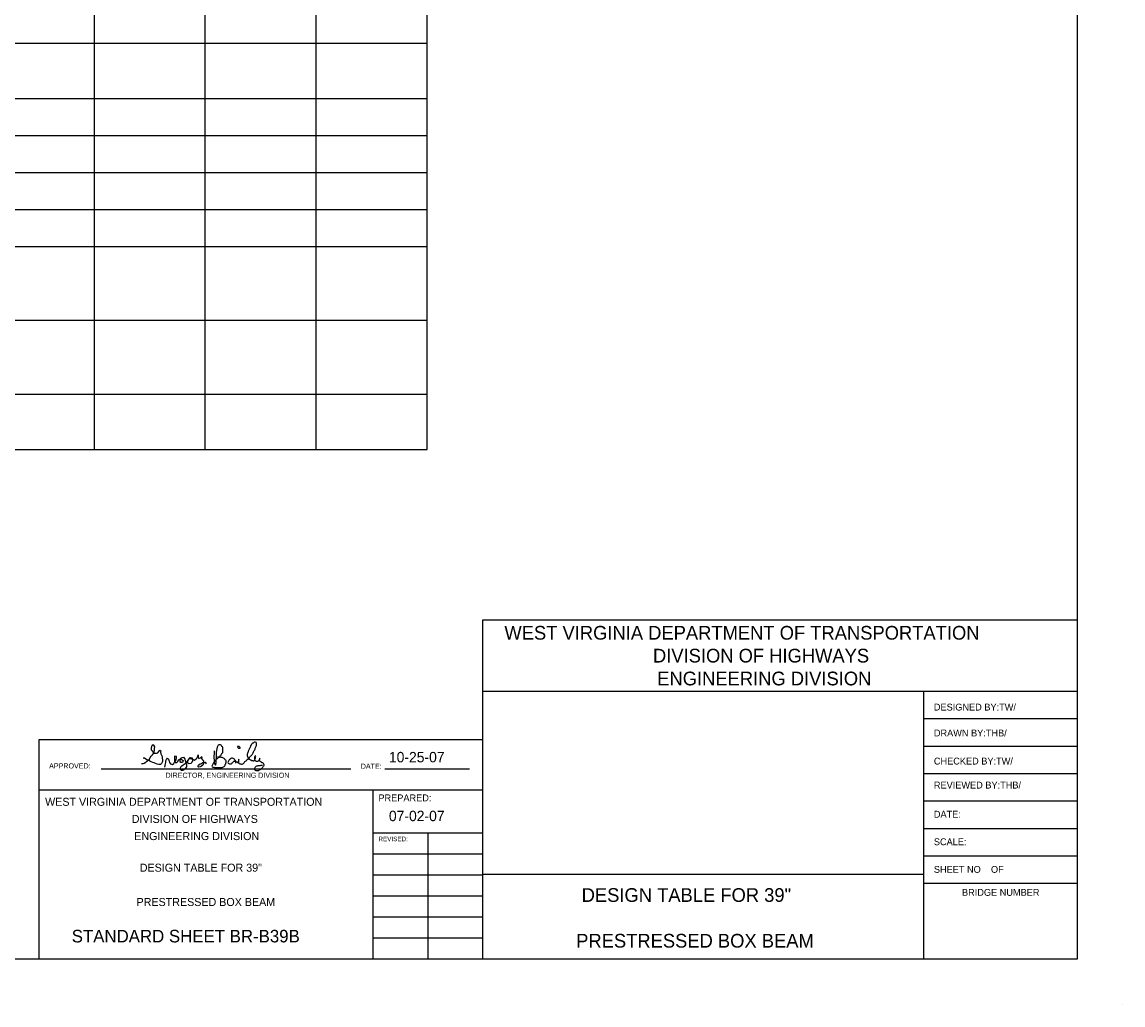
# Model space of a CAD drawing. Extents: x 762.3 to 790.4, y -1210.3 to -1192.2.
# Drawn here: x 780.44 to 790.37, y -1210.35 to -1201.48 of the extents above; entities that cross this region are included whole.
import ezdxf

# ---------------------------------------------------------------- set-up
doc = ezdxf.new("R2010")
doc.units = 0
for name, color, linetype in [('CURBLINE', 7, 'Continuous'), ('Default', 7, 'Continuous'), ('Level 1', 7, 'Continuous')]:
    doc.layers.add(name, color=color, linetype=linetype)

msp = doc.modelspace()

# ---------------------------------------------------------------- linework, layer by layer
at = {"layer": 'CURBLINE'}
msp.add_line((789.9542, -1206.8764), (784.5917, -1206.8755), dxfattribs=at)
at = {"layer": 'Default'}
for p, q in [((789.9542, -1192.6096), (789.9542, -1209.9346)), ((784.0909, -1205.3356), (784.0909, -1193.1689)), ((781.0909, -1205.3356), (781.0909, -1193.6689)), ((782.0909, -1205.3356), (782.0909, -1193.6689)), ((783.0909, -1205.3356), (783.0909, -1193.6689)), ((764.5075, -1201.6689), (784.0909, -1201.6689)), ((764.5075, -1202.1689), (784.0909, -1202.1689)), ((766.2575, -1202.5023), (784.0909, -1202.5023)), ((766.2575, -1202.8356), (784.0909, -1202.8356)), ((764.5075, -1203.1689), (784.0909, -1203.1689)), ((766.2575, -1203.5023), (784.0909, -1203.5023)), ((766.2575, -1204.1689), (784.0909, -1204.1689)), ((764.5075, -1204.8356), (784.0909, -1204.8356)), ((764.5075, -1205.3356), (784.0909, -1205.3356)), ((784.5917, -1206.8755), (784.5917, -1209.9346)), ((784.5917, -1206.9415), (784.5917, -1206.9415)), ((788.5682, -1207.519), (784.5917, -1207.519)), ((788.5682, -1207.519), (788.5682, -1209.9346)), ((789.9542, -1207.519), (788.5682, -1207.519)), ((789.9542, -1207.7665), (788.5682, -1207.7665)), ((784.5917, -1207.9546), (780.5905, -1207.9546)), ((780.5905, -1207.9546), (780.5905, -1209.9346)), ((789.9542, -1208.014), (788.5682, -1208.014)), ((781.152, -1208.2157), (783.4022, -1208.2157)), ((783.7105, -1208.2157), (784.4725, -1208.2157)), ((789.9542, -1208.2615), (788.5682, -1208.2615)), ((783.6017, -1208.4083), (780.5905, -1208.4083)), ((783.6017, -1208.4083), (783.6017, -1209.9346)), ((784.5917, -1208.4083), (783.6017, -1208.4083)), ((789.9542, -1208.509), (788.5682, -1208.509)), ((784.5917, -1208.7961), (783.6017, -1208.7961)), ((784.0967, -1208.7961), (784.0967, -1209.9346)), ((789.9542, -1208.7565), (788.5682, -1208.7565)), ((784.5917, -1208.9858), (783.6017, -1208.9858)), ((789.9542, -1209.004), (788.5682, -1209.004)), ((784.5917, -1209.1756), (783.6017, -1209.1756)), ((788.5682, -1209.169), (784.5917, -1209.169)), ((789.9542, -1209.2515), (788.5682, -1209.2515)), ((784.5917, -1209.3653), (783.6017, -1209.3653)), ((784.5917, -1209.5551), (783.6017, -1209.5551)), ((784.5917, -1209.7448), (783.6017, -1209.7448)), ((789.9542, -1209.9346), (763.5542, -1209.9346)), ((790.3667, -1210.3471), (790.3667, -1210.3471))]:
    msp.add_line(p, q, dxfattribs=at)
at = {"layer": 'Level 1'}
for points in [[(781.516, -1208.1669), (781.531, -1208.1694), (781.5407, -1208.1646), (781.5537, -1208.1568), (781.5637, -1208.1468), (781.5763, -1208.1392), (781.5876, -1208.1279), (781.5938, -1208.1128), (781.6026, -1208.1015), (781.6139, -1208.0915), (781.6227, -1208.0789), (781.629, -1208.0651), (781.6315, -1208.0488), (781.634, -1208.0337), (781.6353, -1208.0186), (781.6265, -1208.0036), (781.6127, -1208.0036), (781.6052, -1208.0149), (781.6026, -1208.0287), (781.6026, -1208.0438), (781.6127, -1208.0538), (781.6215, -1208.0664), (781.634, -1208.0739), (781.6504, -1208.0752), (781.6642, -1208.0726), (781.673, -1208.0613), (781.6818, -1208.0475), (781.6893, -1208.0526), (781.6868, -1208.0664), (781.6906, -1208.0802), (781.6956, -1208.0927), (781.7006, -1208.1053), (781.7031, -1208.1204), (781.7056, -1208.1355), (781.7056, -1208.1505), (781.6968, -1208.1669), (781.6868, -1208.1769), (781.6705, -1208.1769), (781.6579, -1208.1735), (781.6428, -1208.1694), (781.6303, -1208.1618), (781.6177, -1208.1586), (781.6039, -1208.1518), (781.5901, -1208.1468), (781.5788, -1208.1392), (781.5662, -1208.1342), (781.5537, -1208.1292), (781.5423, -1208.1216), (781.5298, -1208.1191)], [(782.1701, -1208.0538), (782.1707, -1208.0607), (782.1707, -1208.0676), (782.1707, -1208.0745), (782.1707, -1208.0821), (782.1695, -1208.089), (782.1682, -1208.0959), (782.1682, -1208.1028), (782.1682, -1208.1097), (782.1682, -1208.1166), (782.1688, -1208.1235), (782.1695, -1208.1304), (782.1695, -1208.1373), (782.1701, -1208.1442), (782.1713, -1208.1512), (782.172, -1208.1587), (782.1726, -1208.1656), (782.1745, -1208.1725), (782.1789, -1208.1775), (782.1826, -1208.1832), (782.1845, -1208.1763), (782.187, -1208.17), (782.1889, -1208.1631), (782.1895, -1208.1562), (782.1895, -1208.1493), (782.1895, -1208.1424), (782.1902, -1208.1355), (782.1902, -1208.1285), (782.1908, -1208.1216), (782.1914, -1208.1147), (782.1921, -1208.1078), (782.1921, -1208.1009), (782.1921, -1208.094), (782.1921, -1208.0871), (782.1921, -1208.0802), (782.1921, -1208.0733), (782.1921, -1208.0664), (782.1927, -1208.0595), (782.1939, -1208.0526), (782.1952, -1208.045), (782.1971, -1208.0381), (782.199, -1208.0312), (782.1996, -1208.0243), (782.2021, -1208.018), (782.2046, -1208.0117), (782.2071, -1208.0054), (782.2109, -1207.9992), (782.2172, -1207.9967), (782.2241, -1207.9973), (782.231, -1207.9992), (782.2354, -1208.0042), (782.2385, -1208.0105), (782.2423, -1208.0161), (782.2454, -1208.0224), (782.2467, -1208.0293), (782.2473, -1208.0362), (782.2473, -1208.0431), (782.2473, -1208.05), (782.2473, -1208.0569), (782.2473, -1208.0639), (782.2461, -1208.0708), (782.2423, -1208.0764), (782.2373, -1208.0808), (782.2329, -1208.0858), (782.2304, -1208.0921), (782.2266, -1208.0978), (782.2228, -1208.1034), (782.2203, -1208.1097), (782.2147, -1208.1135), (782.2084, -1208.1166), (782.2027, -1208.121), (782.1965, -1208.1248), (782.1914, -1208.1292), (782.1864, -1208.1342), (782.1826, -1208.1399), (782.1776, -1208.1442), (782.1738, -1208.1499), (782.1701, -1208.1556), (782.1651, -1208.1612), (782.1613, -1208.1669), (782.1588, -1208.1731), (782.155, -1208.1788), (782.1525, -1208.1851), (782.1512, -1208.192), (782.1538, -1208.1983), (782.16, -1208.2008), (782.1669, -1208.2014), (782.1738, -1208.2033), (782.1808, -1208.2045), (782.1877, -1208.2052), (782.1946, -1208.2052), (782.2021, -1208.2052), (782.209, -1208.2052), (782.2159, -1208.2052), (782.2228, -1208.2052), (782.2297, -1208.2052), (782.2367, -1208.2052), (782.2436, -1208.2052), (782.2486, -1208.2001), (782.2549, -1208.1976), (782.2605, -1208.1939), (782.2662, -1208.1888), (782.2687, -1208.1826), (782.2712, -1208.1763), (782.275, -1208.1706), (782.2775, -1208.1643), (782.2794, -1208.1574), (782.2806, -1208.1505), (782.2806, -1208.1436), (782.2762, -1208.1386), (782.2712, -1208.1342), (782.2662, -1208.1292), (782.2618, -1208.1235), (782.2555, -1208.1198), (782.2492, -1208.116), (782.2423, -1208.1147), (782.2354, -1208.1135), (782.2285, -1208.1122), (782.221, -1208.1122), (782.2134, -1208.1122), (782.2065, -1208.1122), (782.1996, -1208.111), (782.1996, -1208.111)], [(782.3855, -1208.0174), (782.3855, -1208.0243), (782.3905, -1208.0287), (782.3974, -1208.0306), (782.4043, -1208.0299), (782.4056, -1208.023), (782.4006, -1208.0186), (782.3955, -1208.0136), (782.3886, -1208.0136), (782.3824, -1208.0161), (782.3824, -1208.0205)], [(782.486, -1208.1204), (782.4898, -1208.1147), (782.4935, -1208.1091), (782.4973, -1208.1034), (782.5017, -1208.0984), (782.5073, -1208.0946), (782.5117, -1208.0896), (782.5155, -1208.0833), (782.5186, -1208.077), (782.523, -1208.0708), (782.5268, -1208.0645), (782.5293, -1208.0582), (782.5331, -1208.0513), (782.5362, -1208.0444), (782.5394, -1208.0375), (782.5419, -1208.0312), (782.5444, -1208.0249), (782.5469, -1208.0186), (782.5488, -1208.0117), (782.5513, -1208.0054), (782.5526, -1207.9985), (782.5538, -1207.9916), (782.5526, -1207.9847), (782.5482, -1207.9797), (782.5419, -1207.9772), (782.535, -1207.9759), (782.5287, -1207.9797), (782.523, -1207.9835), (782.5168, -1207.986), (782.5117, -1207.9904), (782.508, -1207.996), (782.5042, -1208.0017), (782.4992, -1208.0067), (782.4979, -1208.0136), (782.4954, -1208.0199), (782.4929, -1208.0262), (782.4891, -1208.0318), (782.4866, -1208.0381), (782.4828, -1208.0438), (782.4816, -1208.0507), (782.4778, -1208.0563), (782.4766, -1208.0632), (782.4741, -1208.0701), (782.4715, -1208.077), (782.469, -1208.0833), (782.469, -1208.0902), (782.469, -1208.0971), (782.4703, -1208.1041), (782.4734, -1208.1103), (782.4759, -1208.1172), (782.4791, -1208.1235), (782.4841, -1208.1279), (782.4904, -1208.1304), (782.496, -1208.1348), (782.5029, -1208.1361), (782.5092, -1208.1399), (782.5155, -1208.1424), (782.523, -1208.143), (782.53, -1208.143), (782.5337, -1208.1373), (782.5375, -1208.1317), (782.5406, -1208.1248), (782.5431, -1208.1179), (782.5438, -1208.111), (782.5457, -1208.1034), (782.5406, -1208.099), (782.5381, -1208.1059), (782.5356, -1208.1122), (782.5356, -1208.1191), (782.5356, -1208.126), (782.5356, -1208.1329), (782.5381, -1208.1399), (782.5444, -1208.1436), (782.5507, -1208.1461), (782.5576, -1208.1468), (782.5645, -1208.1468), (782.5708, -1208.1442), (782.5745, -1208.138), (782.5789, -1208.1329), (782.5821, -1208.126), (782.584, -1208.1191), (782.5808, -1208.126), (782.5783, -1208.1323), (782.5758, -1208.1386), (782.5783, -1208.1449), (782.5846, -1208.148), (782.5909, -1208.1512), (782.5953, -1208.1562), (782.6022, -1208.1581), (782.6091, -1208.1606), (782.6135, -1208.1656), (782.616, -1208.1719), (782.6185, -1208.1782), (782.6185, -1208.1851), (782.6172, -1208.192), (782.6122, -1208.1964), (782.6085, -1208.202), (782.6034, -1208.2077), (782.5997, -1208.2133), (782.5934, -1208.2177), (782.5884, -1208.2221), (782.5821, -1208.2259), (782.5758, -1208.2297), (782.5701, -1208.2334), (782.5626, -1208.2341), (782.5557, -1208.2347), (782.5488, -1208.2347), (782.5425, -1208.2309), (782.5387, -1208.2253), (782.5375, -1208.2184), (782.5381, -1208.2114), (782.54, -1208.2045), (782.5438, -1208.1983), (782.5482, -1208.1932), (782.5544, -1208.1907), (782.5607, -1208.1882), (782.5676, -1208.187), (782.5745, -1208.187), (782.5815, -1208.1857), (782.5884, -1208.1857), (782.5953, -1208.1844), (782.6022, -1208.1832), (782.6059, -1208.1819)], [(781.7261, -1208.2008), (781.7298, -1208.1863), (781.7317, -1208.1725), (781.7336, -1208.1587), (781.7361, -1208.1449), (781.7411, -1208.1311), (781.7493, -1208.1198), (781.76, -1208.1279), (781.7662, -1208.1468), (781.7688, -1208.1606), (781.7776, -1208.1706), (781.7958, -1208.1775), (781.8058, -1208.1681), (781.8146, -1208.1568), (781.8228, -1208.1461), (781.8272, -1208.1329), (781.8322, -1208.1198), (781.8303, -1208.1059), (781.8121, -1208.1034), (781.8121, -1208.1172), (781.8121, -1208.1311), (781.814, -1208.1449), (781.819, -1208.1581), (781.8347, -1208.1593), (781.8435, -1208.1493), (781.8479, -1208.1355), (781.8605, -1208.1298), (781.8743, -1208.1298), (781.89, -1208.1417), (781.8856, -1208.1593), (781.8718, -1208.1606), (781.8642, -1208.1493), (781.8648, -1208.1348), (781.8692, -1208.121), (781.8812, -1208.1147), (781.895, -1208.1122), (781.9063, -1208.1285), (781.9101, -1208.1424), (781.9138, -1208.1556), (781.9182, -1208.1687), (781.9201, -1208.1826), (781.9201, -1208.197), (781.9101, -1208.214), (781.8994, -1208.2228), (781.8875, -1208.2303), (781.8736, -1208.2309), (781.868, -1208.2121), (781.8718, -1208.1989), (781.8806, -1208.1888), (781.8902, -1208.1817), (781.9006, -1208.1731), (781.9176, -1208.1631), (781.9314, -1208.1486), (781.9362, -1208.1373), (781.9459, -1208.1248), (781.954, -1208.1141), (781.9722, -1208.1179), (781.9754, -1208.1317), (781.9754, -1208.1455), (781.9704, -1208.1587), (781.9597, -1208.1669), (781.9465, -1208.1713), (781.9346, -1208.165), (781.9321, -1208.1518), (781.9352, -1208.1386), (781.9434, -1208.1273), (781.9559, -1208.1223), (781.9741, -1208.1304), (781.9923, -1208.1367), (782.008, -1208.1267), (782.0162, -1208.116), (782.0231, -1208.1034), (782.0281, -1208.0896), (782.0281, -1208.0965), (782.0269, -1208.1103), (782.0325, -1208.1229), (782.0489, -1208.1185), (782.0577, -1208.1078), (782.0589, -1208.1084), (782.057, -1208.1223), (782.0646, -1208.1348), (782.0746, -1208.1442), (782.0752, -1208.1581), (782.0752, -1208.1719), (782.0677, -1208.1832), (782.0577, -1208.1926), (782.0445, -1208.1983), (782.0313, -1208.2014), (782.0231, -1208.1907), (782.0319, -1208.1788), (782.0438, -1208.1706), (782.0577, -1208.1681), (782.069, -1208.1606), (782.0884, -1208.1568), (782.0985, -1208.1725), (782.0997, -1208.1719)], [(782.366, -1208.1662), (782.3673, -1208.1593), (782.3673, -1208.1524), (782.3673, -1208.1455), (782.3616, -1208.1405), (782.3566, -1208.1355), (782.3528, -1208.1298), (782.3472, -1208.126), (782.3415, -1208.1223), (782.3353, -1208.1198), (782.3283, -1208.1198), (782.3214, -1208.1223), (782.3164, -1208.1267), (782.3108, -1208.1311), (782.3057, -1208.1355), (782.302, -1208.1411), (782.2995, -1208.1474), (782.2957, -1208.153), (782.2932, -1208.1593), (782.2976, -1208.1643), (782.302, -1208.1694), (782.3095, -1208.1713), (782.3164, -1208.1713), (782.3233, -1208.1713), (782.3296, -1208.1687), (782.334, -1208.1631), (782.3384, -1208.1581), (782.3428, -1208.1524), (782.3491, -1208.1486), (782.3566, -1208.1486), (782.3641, -1208.1493), (782.3704, -1208.1518), (782.3767, -1208.1543), (782.3824, -1208.1581), (782.3893, -1208.1581), (782.3912, -1208.1512), (782.393, -1208.1442), (782.3937, -1208.1367), (782.3937, -1208.1298), (782.3912, -1208.1361), (782.3899, -1208.143), (782.3899, -1208.1499), (782.3899, -1208.1568), (782.3905, -1208.1637), (782.3968, -1208.1669), (782.4031, -1208.1706), (782.41, -1208.1725), (782.4169, -1208.1731), (782.4238, -1208.1731), (782.4307, -1208.1719), (782.4364, -1208.1681), (782.4401, -1208.1618), (782.4452, -1208.1574), (782.4489, -1208.1512), (782.454, -1208.1468), (782.4596, -1208.143), (782.4646, -1208.138), (782.4697, -1208.1329), (782.4753, -1208.1292), (782.481, -1208.1254), (782.4847, -1208.1204)]]:
    msp.add_lwpolyline(points, dxfattribs=at)

# ---------------------------------------------------------------- texts
at = {"layer": 'Default'}
for s, height, p in [('WEST VIRGINIA DEPARTMENT OF TRANSPORTATION', 0.12375, (784.7884, -1207.0508)), ('DIVISION OF HIGHWAYS', 0.12375, (786.1282, -1207.2571)), ('ENGINEERING DIVISION', 0.12375, (786.1667, -1207.4633)), ('DESIGNED BY:TW/', 0.061875, (788.6613, -1207.6904)), ('DRAWN BY:THB/', 0.061875, (788.6613, -1207.9241)), ('10-25-07', 0.09375, (783.7469, -1208.1578)), ('CHECKED BY:TW/', 0.061875, (788.6613, -1208.1776)), ('APPROVED:                                                  ', 0.046406, (780.6826, -1208.2129)), ('DATE:', 0.04641, (783.493, -1208.2157)), ('DIRECTOR, ENGINEERING DIVISION', 0.046406, (781.7318, -1208.2974)), ('REVIEWED BY:THB/', 0.061875, (788.6613, -1208.3941)), ('WEST VIRGINIA DEPARTMENT OF TRANSPORTATION', 0.072188, (780.6464, -1208.5498)), ('PREPARED:', 0.06187, (783.6523, -1208.5093)), ('07-02-07', 0.09375, (783.7469, -1208.6882)), ('DATE:', 0.06187, (788.6613, -1208.6568)), ('DIVISION OF HIGHWAYS', 0.072188, (781.4279, -1208.7045)), ('ENGINEERING DIVISION', 0.072188, (781.4504, -1208.8592)), ('REVISED:', 0.04125, (783.6523, -1208.8696)), ('SCALE:', 0.06187, (788.6613, -1208.9056)), ('DESIGN TABLE FOR 39"', 0.072188, (781.4998, -1209.1444)), ('SHEET NO    OF', 0.061875, (788.6613, -1209.1545)), ('DESIGN TABLE FOR 39"', 0.12375, (785.485, -1209.4168)), ('BRIDGE NUMBER', 0.061875, (788.9148, -1209.3619)), ('PRESTRESSED BOX BEAM', 0.072188, (781.4711, -1209.4538)), ('STANDARD SHEET BR-B39B', 0.113437, (780.8864, -1209.7825)), ('PRESTRESSED BOX BEAM', 0.12375, (785.4357, -1209.8293))]:
    msp.add_text(s, height=height, dxfattribs=at).set_placement(p)

doc.saveas('drawing.dxf')
